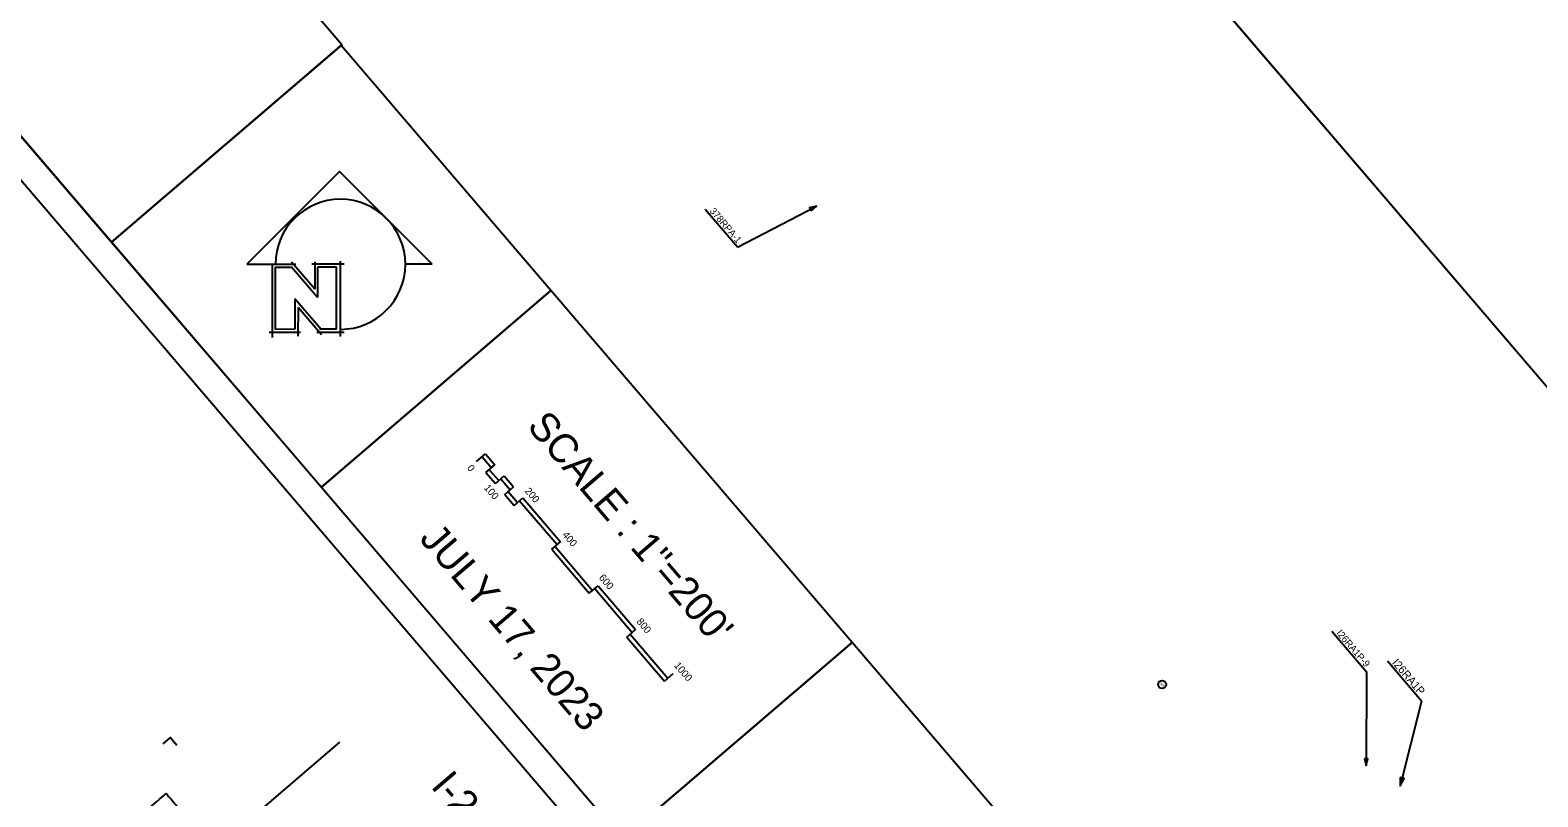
# Model space of a CAD drawing. Extents: x 1941897 to 1978064, y 805467 to 836604.
# Drawn here: x 1956688 to 1961909, y 810856 to 813509 of the extents above; entities that cross this region are included whole.
import ezdxf

# ---------------------------------------------------------------- set-up
doc = ezdxf.new("R2010")
doc.units = 0
for name, color, linetype in [('RD_EX_DV_TX_Prop', 7, 'Continuous'), ('RD_EX_H20_TX', 7, 'Continuous'), ('RD_SHT_Bndy', 7, 'Continuous'), ('RD_SHT_IplotShp', 7, 'Continuous'), ('RD_SHT_MatchLine', 7, 'Continuous'), ('RD_SHT_Misc2', 7, 'Continuous'), ('RD_SHT_ShtClip', 7, 'Continuous'), ('RD_SHT_TX', 7, 'Continuous'), ('RD_TX_RoadID', 7, 'Continuous')]:
    doc.layers.add(name, color=color, linetype=linetype)

msp = doc.modelspace()

# ---------------------------------------------------------------- linework, layer by layer
at = {"layer": 'RD_EX_DV_TX_Prop'}
msp.add_circle((1960607.9, 811244.6), 13.8, dxfattribs=at)
at = {"layer": 'RD_EX_H20_TX'}
for points in [[(1963151.2, 810860.3), (1959509.3, 815114.3), (1958096.8, 813905.1), (1957040.5, 814307.7), (1947588.1, 825348.6), (1952108, 829218.2), (1965848, 813169.1)], [(1963151.2, 810860.3), (1959509.3, 815114.3), (1958096.8, 813905.1), (1957040.5, 814307.7), (1947588.1, 825348.6), (1952108, 829218.2), (1965848, 813169.1)], [(1963151.2, 810860.3), (1959509.3, 815114.3), (1958096.8, 813905.1), (1957040.5, 814307.7), (1947588.1, 825348.6), (1952108, 829218.2), (1965848, 813169.1)], [(1963151.2, 810860.3), (1959509.3, 815114.3), (1958096.8, 813905.1), (1957040.5, 814307.7), (1949323.3, 823321.8), (1953668.8, 827395), (1965848, 813169.1)], [(1963151.2, 810860.3), (1959509.3, 815114.3), (1958096.8, 813905.1), (1957040.5, 814307.7), (1949323.3, 823321.8), (1953668.8, 827395), (1965848, 813169.1)], [(1963151.2, 810860.3), (1959509.3, 815114.3), (1958096.8, 813905.1), (1957040.5, 814307.7), (1949323.3, 823321.8), (1953668.8, 827395), (1965848, 813169.1)]]:
    msp.add_lwpolyline(points, close=True, dxfattribs=at)
at = {"layer": 'RD_SHT_Bndy'}
for points in [[(1960707.9, 808409.5), (1943668.8, 828312), (1948986.3, 832864.4), (1966025.3, 812961.9)], [(1946512.2, 824990.8), (1956970, 812775.5), (1957767.7, 813458.3), (1947309.9, 825673.6)], [(1956970, 812775.5), (1957696.5, 811926.9), (1958491.3, 812607.4), (1957764.9, 813455.9)], [(1957696.5, 811926.9), (1958739.3, 810708.9), (1959534.1, 811389.4), (1958491.3, 812607.4)], [(1958739.3, 810708.9), (1960707.9, 808409.5), (1961502.7, 809090), (1959534.1, 811389.4)]]:
    msp.add_lwpolyline(points, close=True, dxfattribs=at)
at = {"layer": 'RD_SHT_IplotShp'}
msp.add_lwpolyline([(1960696.9, 808268.5), (1943527.9, 828323), (1948997.3, 833005.4), (1966166.3, 812950.9)], close=True, dxfattribs=at)
at = {"layer": 'RD_SHT_MatchLine'}
msp.add_line((1959509.3, 815114.3), (1963151.2, 810860.3), dxfattribs=at)
at = {"layer": 'RD_SHT_Misc2'}
msp.add_lwpolyline([(1957148.3, 811038.7), (1957173.9, 811060.7), (1957195.9, 811035)], dxfattribs=at)
msp.add_open_spline([(1957186.8, 810665.7), (1957186.8, 810665.7), (1957111.7, 810753.5), (1957111.7, 810753.5), (1957111.7, 810753.5), (1957111.7, 810753.5), (1957195.1, 810824.9), (1957195.1, 810824.9), (1957195.1, 810824.9), (1957195.1, 810824.9), (1957158.9, 810867.1), (1957158.9, 810867.1), (1957158.9, 810867.1), (1957158.9, 810867.1), (1956950.4, 810688.6), (1956950.4, 810688.6), (1956950.4, 810688.6), (1956950.4, 810688.6), (1956986.6, 810646.3), (1956986.6, 810646.3), (1956986.6, 810646.3), (1956986.6, 810646.3), (1957070, 810717.8), (1957070, 810717.8), (1957070, 810717.8), (1957070, 810717.8), (1957145.1, 810630), (1957145.1, 810630), (1957145.1, 810630), (1957145.1, 810630), (1957186.8, 810665.7), (1957186.8, 810665.7)], degree=3, dxfattribs=at)
at = {"layer": 'RD_SHT_ShtClip'}
msp.add_line((1957759.5, 811045), (1956702.2, 810139.9), dxfattribs=at)
at = {"layer": 'RD_SHT_TX'}
for p, q in [((1957759, 813019.5), (1957437.9, 812698.4)), ((1958080.1, 812698.4), (1957759, 813019.5)), ((1957437.9, 812698.4), (1957537.3, 812698.4)), ((1957525.6, 812698.4), (1957525.6, 812445.3)), ((1957536.8, 812698.4), (1957607.5, 812698.6)), ((1957673.7, 812612.6), (1957593.2, 812705.9)), ((1957775.9, 812699), (1957663, 812698.7)), ((1957673.7, 812706.8), (1957673.7, 812612.6)), ((1957762.3, 812448.1), (1957762.3, 812709.5)), ((1957762.3, 812699), (1957762.3, 812699)), ((1958080.1, 812698.4), (1957987.3, 812698.4)), ((1957536.8, 812688.1), (1957593.5, 812688.3)), ((1957536.8, 812688.1), (1957536.8, 812473.4)), ((1957683.6, 812583.8), (1957593.5, 812688.3)), ((1957749.2, 812688.6), (1957683.6, 812688.5)), ((1957683.6, 812688.5), (1957683.6, 812583.8)), ((1957749.3, 812474), (1957749.2, 812688.6)), ((1957695.4, 812473.3), (1957604.3, 812578.9)), ((1957604.3, 812578.9), (1957604.3, 812473.6)), ((1957615.6, 812548.6), (1957615.5, 812449.9)), ((1957697.1, 812454.1), (1957615.6, 812548.6)), ((1957624.3, 812462.4), (1957516.1, 812462.1)), ((1957604.3, 812473.6), (1957537.3, 812473.4)), ((1957775.9, 812462.2), (1957681, 812462)), ((1957749.3, 812474), (1957690.2, 812473.8)), ((1958234, 812016), (1958264.4, 812042.1)), ((1958253, 812032.3), (1958285.5, 811994.3)), ((1958264.4, 812042.1), (1958296.9, 812004.1)), ((1958266.5, 811978.1), (1958296.9, 812004.1)), ((1958266.5, 811978.1), (1958299.1, 811940.1)), ((1958277.9, 811987.8), (1958310.5, 811949.8)), ((1958299.1, 811940.1), (1958329.5, 811966.1)), ((1958329.5, 811966.1), (1958362, 811928.1)), ((1958318.1, 811956.3), (1958350.6, 811918.4)), ((1958331.6, 811902.1), (1958362, 811928.1)), ((1958343, 811911.9), (1958375.5, 811873.9)), ((1958331.6, 811902.1), (1958364.1, 811864.1)), ((1958364.1, 811864.1), (1958394.5, 811890.1)), ((1958383.1, 811880.4), (1958513.2, 811728.4)), ((1958394.5, 811890.1), (1958524.6, 811738.2)), ((1958494.2, 811712.2), (1958524.6, 811738.2)), ((1958494.2, 811712.2), (1958624.2, 811560.3)), ((1958505.6, 811721.9), (1958635.6, 811570)), ((1958624.2, 811560.3), (1958654.6, 811586.3)), ((1958643.2, 811576.5), (1958773.3, 811424.6)), ((1958654.6, 811586.3), (1958784.7, 811434.3)), ((1958754.3, 811408.3), (1958784.7, 811434.3)), ((1958754.3, 811408.3), (1958884.4, 811256.4)), ((1958765.7, 811418.1), (1958895.8, 811266.2)), ((1958884.4, 811256.4), (1958914.8, 811282.4))]:
    msp.add_line(p, q, dxfattribs=at)
msp.add_arc((1957762.3, 812698.4), 225, 270.0008, 180, dxfattribs=at)
at = {"layer": 'RD_TX_RoadID'}
for p, q in [((1959137, 812757.3), (1959025.2, 812887.8)), ((1961316.7, 811286), (1961195.6, 811427.4)), ((1961506.2, 811186.9), (1961388, 811324.9))]:
    msp.add_line(p, q, dxfattribs=at)
for points in [[(1959137, 812757.3), (1959410.9, 812899.2)], [(1961316.4, 811285.7), (1961314.6, 810964.6)], [(1961506.2, 811186.9), (1961432.8, 810894.1)]]:
    msp.add_lwpolyline(points, dxfattribs=at)
for points in [[(1959393.1, 812883), (1959410.9, 812899.2), (1959387.4, 812894.1)], [(1961308.5, 810987.8), (1961314.6, 810964.6), (1961321, 810987.7)], [(1961432.4, 810922.1), (1961432.8, 810894.1), (1961446.4, 810918.6)]]:
    msp.add_lwpolyline(points, close=True, dxfattribs=at)

# ---------------------------------------------------------------- texts
at = {"layer": 'RD_EX_DV_TX_Prop'}
msp.add_text('506', height=8, rotation=325.8726, dxfattribs=at).set_placement((1960598.5, 811246.1))
at = {"layer": 'RD_SHT_TX'}
for s, height, p in [('SCALE : 1"=200\'', 100, (1958405.4, 812136)), ('0', 25, (1958199.6, 811992.4)), ('100', 25, (1958258.1, 811924.1)), ('200', 25, (1958399.1, 811913.1)), ('JULY 17, 2023', 100, (1958032.7, 811747.1)), ('400', 25, (1958529.2, 811761.2)), ('600', 25, (1958656, 811613.1)), ('800', 25, (1958786.1, 811461.1)), ('1000', 25, (1958916.2, 811309.2)), ('I-26 (WEST OF I-20)', 100, (1958072.6, 810890.8))]:
    msp.add_text(s, height=height, rotation=310.5675, dxfattribs=at).set_placement(p)
at = {"layer": 'RD_TX_RoadID'}
for s, height, p in [('378RPA-1', 24, (1959039.6, 812881.7)), ('I26RA1P-9', 24, (1961210, 811421.3)), ('I26RA1P', 28, (1961402.4, 811318.8))]:
    msp.add_text(s, height=height, rotation=310.5675, dxfattribs=at).set_placement(p)

doc.saveas('drawing.dxf')
